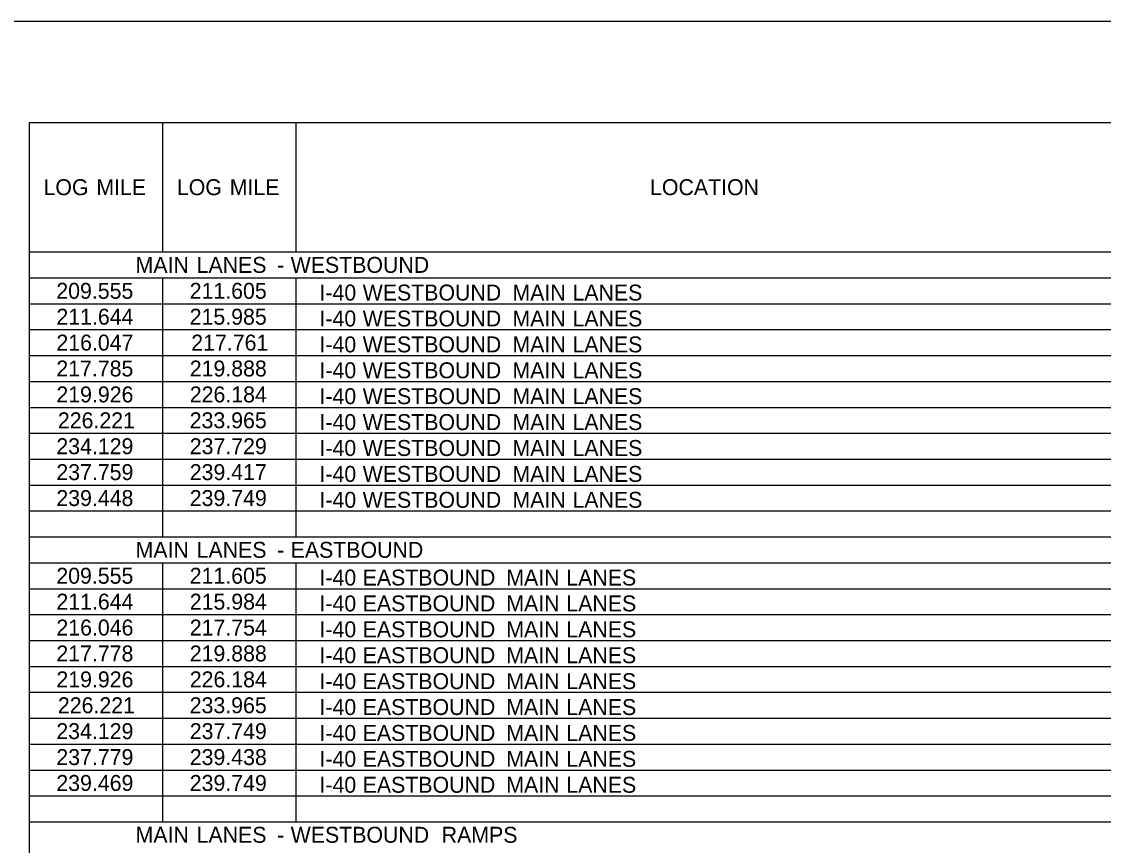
# Model space of a CAD drawing. Extents: x 2261867 to 2275370, y -3124789 to -3122260.
# Drawn here: x 2269397.5 to 2269764, y -3123902.3 to -3123623.2 of the extents above; entities that cross this region are included whole.
import ezdxf

# ---------------------------------------------------------------- set-up
doc = ezdxf.new("R2010")
doc.units = 0
doc.layers.add('Default', color=7, linetype='Continuous')
doc.layers.add('DSN_DRFT_Named-Boundary', color=7, linetype='Continuous')

msp = doc.modelspace()

# ---------------------------------------------------------------- linework, layer by layer
at = {"layer": 'Default'}
for p, q in [((2269400.16, -3123657.37), (2270414.11, -3123657.37)), ((2269400.16, -3124701.59), (2269400.16, -3123657.37)), ((2269400.16, -3124701.59), (2269400.16, -3123657.37)), ((2269445.35, -3123701.24), (2269445.35, -3123657.37)), ((2269490.54, -3123701.24), (2269490.54, -3123657.37)), ((2269400.16, -3123701.24), (2270414.11, -3123701.24)), ((2269400.16, -3123710.02), (2270414.11, -3123710.02)), ((2269445.35, -3123797.77), (2269445.35, -3123710.02)), ((2269445.35, -3123797.77), (2269445.35, -3123710.02)), ((2269490.54, -3123797.77), (2269490.54, -3123710.02)), ((2269490.54, -3123797.77), (2269490.54, -3123710.02)), ((2269400.16, -3123718.79), (2270414.11, -3123718.79)), ((2269400.16, -3123727.57), (2270414.11, -3123727.57)), ((2269400.16, -3123736.34), (2270414.11, -3123736.34)), ((2269400.16, -3123745.12), (2270414.11, -3123745.12)), ((2269400.16, -3123753.89), (2270414.11, -3123753.89)), ((2269400.16, -3123762.67), (2270414.11, -3123762.67)), ((2269400.16, -3123771.44), (2270414.11, -3123771.44)), ((2269400.16, -3123780.22), (2270414.11, -3123780.22)), ((2269400.16, -3123788.99), (2270414.11, -3123788.99)), ((2269400.16, -3123797.77), (2270414.11, -3123797.77)), ((2269400.16, -3123797.77), (2270414.11, -3123797.77)), ((2269400.16, -3123806.54), (2270414.11, -3123806.54)), ((2269445.35, -3123894.29), (2269445.35, -3123806.54)), ((2269445.35, -3123894.29), (2269445.35, -3123806.54)), ((2269490.54, -3123894.29), (2269490.54, -3123806.54)), ((2269490.54, -3123894.29), (2269490.54, -3123806.54)), ((2269400.16, -3123815.32), (2270414.11, -3123815.32)), ((2269400.16, -3123824.09), (2270414.11, -3123824.09)), ((2269400.16, -3123832.87), (2270414.11, -3123832.87)), ((2269400.16, -3123841.64), (2270414.11, -3123841.64)), ((2269400.16, -3123850.42), (2270414.11, -3123850.42)), ((2269400.16, -3123859.19), (2270414.11, -3123859.19)), ((2269400.16, -3123867.97), (2270414.11, -3123867.97)), ((2269400.16, -3123876.74), (2270414.11, -3123876.74)), ((2269400.16, -3123885.52), (2270414.11, -3123885.52)), ((2269400.16, -3123894.29), (2270414.11, -3123894.29)), ((2269400.16, -3123894.29), (2270414.11, -3123894.29))]:
    msp.add_line(p, q, dxfattribs=at)
at = {"layer": 'DSN_DRFT_Named-Boundary'}
msp.add_lwpolyline([(2269094.64, -3124789.38), (2270719.64, -3124789.38), (2270719.64, -3123623.23), (2269094.64, -3123623.23)], close=True, dxfattribs=at)

# ---------------------------------------------------------------- texts
at = {"layer": 'Default'}
for s, p in [('LOG', (2269404.94, -3123682.01)), (' MILE', (2269420.83, -3123682.01)), ('LOG', (2269450.13, -3123682.01)), (' MILE', (2269466.02, -3123682.01)), ('LOCATION', (2269610.45, -3123682.01)), ('MAIN', (2269436.14, -3123708.33)), (' LANES', (2269454.81, -3123708.33)), (' WESTBOUND', (2269486.67, -3123708.33)), (' -', (2269482.11, -3123708.33)), ('209.555', (2269409.28, -3123717.11)), ('211.605', (2269454.47, -3123717.11)), ('I-40', (2269498.44, -3123717.71)), (' WESTBOUND', (2269511.07, -3123717.71)), (' MAIN', (2269561.81, -3123717.71)), (' LANES', (2269582.15, -3123717.71)), ('211.644', (2269409.31, -3123725.88)), ('215.985', (2269454.47, -3123725.88)), ('I-40', (2269498.44, -3123726.49)), (' WESTBOUND', (2269511.07, -3123726.49)), (' MAIN', (2269561.81, -3123726.49)), (' LANES', (2269582.15, -3123726.49)), ('216.047', (2269409.3, -3123734.66)), ('217.761', (2269455.01, -3123734.66)), ('I-40', (2269498.44, -3123735.26)), (' WESTBOUND', (2269511.07, -3123735.26)), (' MAIN', (2269561.81, -3123735.26)), (' LANES', (2269582.15, -3123735.26)), ('217.785', (2269409.28, -3123743.43)), ('219.888', (2269454.49, -3123743.43)), ('I-40', (2269498.44, -3123744.04)), (' WESTBOUND', (2269511.07, -3123744.04)), (' MAIN', (2269561.81, -3123744.04)), (' LANES', (2269582.15, -3123744.04)), ('219.926', (2269409.3, -3123752.21)), ('226.184', (2269454.5, -3123752.21)), ('I-40', (2269498.44, -3123752.81)), (' WESTBOUND', (2269511.07, -3123752.81)), (' MAIN', (2269561.81, -3123752.81)), (' LANES', (2269582.15, -3123752.81)), ('226.221', (2269409.82, -3123760.98)), ('233.965', (2269454.47, -3123760.98)), ('I-40', (2269498.44, -3123761.59)), (' WESTBOUND', (2269511.07, -3123761.59)), (' MAIN', (2269561.81, -3123761.59)), (' LANES', (2269582.15, -3123761.59)), ('234.129', (2269409.29, -3123769.76)), ('237.729', (2269454.49, -3123769.76)), ('I-40', (2269498.44, -3123770.36)), (' WESTBOUND', (2269511.07, -3123770.36)), (' MAIN', (2269561.81, -3123770.36)), (' LANES', (2269582.15, -3123770.36)), ('237.759', (2269409.29, -3123778.53)), ('239.417', (2269454.49, -3123778.53)), ('I-40', (2269498.44, -3123779.14)), (' WESTBOUND', (2269511.07, -3123779.14)), (' MAIN', (2269561.81, -3123779.14)), (' LANES', (2269582.15, -3123779.14)), ('239.448', (2269409.29, -3123787.31)), ('239.749', (2269454.49, -3123787.31)), ('I-40', (2269498.44, -3123787.91)), (' WESTBOUND', (2269511.07, -3123787.91)), (' MAIN', (2269561.81, -3123787.91)), (' LANES', (2269582.15, -3123787.91)), (' LANES', (2269454.81, -3123804.86)), (' EASTBOUND', (2269486.67, -3123804.86)), ('MAIN', (2269436.14, -3123804.86)), (' -', (2269482.11, -3123804.86)), ('209.555', (2269409.28, -3123813.63)), ('211.605', (2269454.47, -3123813.63)), ('I-40', (2269498.44, -3123814.24)), (' EASTBOUND', (2269511.07, -3123814.24)), (' MAIN', (2269559.73, -3123814.24)), (' LANES', (2269580.07, -3123814.24)), ('211.644', (2269409.31, -3123822.41)), ('215.984', (2269454.5, -3123822.41)), ('I-40', (2269498.44, -3123823.01)), (' EASTBOUND', (2269511.07, -3123823.01)), (' MAIN', (2269559.73, -3123823.01)), (' LANES', (2269580.07, -3123823.01)), ('216.046', (2269409.3, -3123831.18)), ('217.754', (2269454.5, -3123831.18)), ('I-40', (2269498.44, -3123831.79)), (' EASTBOUND', (2269511.07, -3123831.79)), (' MAIN', (2269559.73, -3123831.79)), (' LANES', (2269580.07, -3123831.79)), ('217.778', (2269409.29, -3123839.96)), ('219.888', (2269454.49, -3123839.96)), ('I-40', (2269498.44, -3123840.56)), (' EASTBOUND', (2269511.07, -3123840.56)), (' MAIN', (2269559.73, -3123840.56)), (' LANES', (2269580.07, -3123840.56)), ('219.926', (2269409.3, -3123848.73)), ('226.184', (2269454.5, -3123848.73)), ('I-40', (2269498.44, -3123849.34)), (' EASTBOUND', (2269511.07, -3123849.34)), (' MAIN', (2269559.73, -3123849.34)), (' LANES', (2269580.07, -3123849.34)), ('226.221', (2269409.82, -3123857.51)), ('233.965', (2269454.47, -3123857.51)), ('I-40', (2269498.44, -3123858.11)), (' EASTBOUND', (2269511.07, -3123858.11)), (' MAIN', (2269559.73, -3123858.11)), (' LANES', (2269580.07, -3123858.11)), ('234.129', (2269409.29, -3123866.28)), ('237.749', (2269454.49, -3123866.28)), ('I-40', (2269498.44, -3123866.89)), (' EASTBOUND', (2269511.07, -3123866.89)), (' MAIN', (2269559.73, -3123866.89)), (' LANES', (2269580.07, -3123866.89)), ('237.779', (2269409.29, -3123875.06)), ('239.438', (2269454.49, -3123875.06)), ('I-40', (2269498.44, -3123875.66)), (' EASTBOUND', (2269511.07, -3123875.66)), (' MAIN', (2269559.73, -3123875.66)), (' LANES', (2269580.07, -3123875.66)), ('239.469', (2269409.29, -3123883.83)), ('239.749', (2269454.49, -3123883.83)), ('I-40', (2269498.44, -3123884.44)), (' EASTBOUND', (2269511.07, -3123884.44)), (' MAIN', (2269559.73, -3123884.44)), (' LANES', (2269580.07, -3123884.44)), ('MAIN', (2269436.14, -3123901.38)), (' LANES', (2269454.81, -3123901.38)), (' WESTBOUND', (2269486.67, -3123901.38)), (' RAMPS', (2269537.85, -3123901.38)), (' -', (2269482.11, -3123901.38))]:
    msp.add_text(s, height=5.4, dxfattribs=at).set_placement(p)

doc.saveas('drawing.dxf')
